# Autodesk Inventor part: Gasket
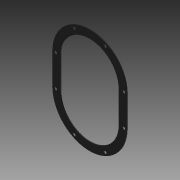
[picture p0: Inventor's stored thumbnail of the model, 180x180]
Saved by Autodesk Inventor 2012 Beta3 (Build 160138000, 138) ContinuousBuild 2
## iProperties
Created: 2010-12
Part Number: Gasket
Material: Rubber
Document SubType Name: Modeling
Designer: Thom Tremblay
Mass: 7.85962 g
Surface Area: 147.076 cm^2
Volume: 8.4512 cm^3
Density: 0.93 g/cm^3
Author: Thom Tremblay
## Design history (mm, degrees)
sketch "Sketch1"
  geometry: L1 (-60, 33.338)-(-60, -16.662) reference; L2 (60, -16.662)-(60, 33.338) reference; L3 (-46.998, -16.662)-(-46.998, 33.338) reference; L4 (46.998, 33.338)-(46.998, -16.662) reference; C1 r 1.621 at (-55, -17.463) reference; C2 r 1.621 at (-25, -66.452) reference; C3 r 1.621 at (25, -66.452) reference; C4 r 1.621 at (55, -17.462) reference; C5 r 1.621 at (55, 33.338) reference; C6 r 1.621 at (25, 82.327) reference; C7 r 1.621 at (-25, 82.327) reference; C8 r 1.621 at (-55, 33.337) reference; A1 r 60 centre (0, -16.662) between (-60, -16.662) and (-18.704, -73.673) reference; A2 r 60 centre (0, 33.338) between (60, 33.338) and (-60, 33.338) reference; A3 r 46.998 centre (0, -16.662) between (-46.998, -16.662) and (46.998, -16.662) reference; A4 r 46.998 centre (0, 33.338) between (46.998, 33.338) and (-46.998, 33.338) reference; A5 r 60.082 centre (0, -16.662) between (-16.251, -74.505) and (16.251, -74.505) reference; A6 r 60 centre (0, -16.662) between (18.704, -73.673) and (60, -16.662) reference; 21 further points
extrude "Extrusion1" new body sketch "Sketch1" distance "d0" = 1.27; taper "d1" = 0 deg
node "Hole3"
body "Solid1"
node "Reference1"
sketch "Sketch3"
  geometry: 8 further points
hole "Hole2" sketch "Sketch3" diameter "d9" = 4.49999; stored, may be unused: countersink angle "d13" = 82 deg, drill point angle "d15" = 0 deg; dims "d10" = 19.05, "d11" = 9.525, "d12" = 6.35, "d14" = 25.4
